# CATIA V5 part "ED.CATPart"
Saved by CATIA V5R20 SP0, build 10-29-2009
Part number: ED
Material "Or": density 19320 kg/m3, Young's modulus 7.8e+10 Pa, Poisson ratio 0.42, thermal expansion 1.42e-05 1/K
Bounding box of the stored display mesh (mm): x -35.216 to 14.383, y -1.883 to 23.533, z 0 to 2
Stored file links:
  D:\IAO\22janv\ED.CATPart
  D:\IAO\22janv\czortea.CATProduct
  C:\Program Files\Dassault Systemes\B20\win_b64\startup\materials\French\Catalog.CATMaterial
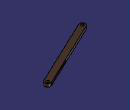
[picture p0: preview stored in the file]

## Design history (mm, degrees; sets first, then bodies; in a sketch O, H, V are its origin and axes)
External parameters (linked from other documents)
  External.epaisseur = 2 mm
Set1
  Plane1 "plan_ref": linked copy from another document
  Point1 "E": linked copy from another document
  Point2 "D": linked copy from another document
Body1 (main body), material "Or"
  Sketch1 on Plane1, origin (0, 0, 0), H (1, 0, 0), V (0, 1, 0)
    construction line L1 (-33.3333, 0) -> (12.5, 21.6506)
    point P1 (-33.3333, 0)
    point P2 (12.5, 21.6506)
    line L2 (-34.1876, 1.8084) -> (11.6458, 23.459)
    line L3 (13.3542, 19.8422) -> (-32.4791, -1.8084)
    arc A1 centre (12.5, 21.6506) radius 2 from (11.6458, 23.459) to (13.3542, 19.8422) cw
    arc A2 centre (-33.3333, 0) radius 2 from (-32.4791, -1.8084) to (-34.1876, 1.8084) cw
    reference projected point E1 (-33.3333, 0) from Point1
    reference projected point E2 (12.5, 21.6506) from Point2
    distance L1 L2 = 2 {= External.epaisseur}
    tangency: A1 L2, A2 L2, A1 L3, A2 L3
    coincidence: P1 E1, P2 E2
  Pad1: profile Sketch1, direction (0, 0, 1), length 2 {= External.epaisseur}
  Sketch2 on end face of Pad1, origin (-13.8524, 8.1093, 2), H (1, 0, 0), V (0, 1, 0)
    point P1 (26.3524, 13.5413)
    reference projected point E1 (26.3524, 13.5413) from Point2
    coincidence: P1 E1
  Hole1: placed by Sketch2, at (12.5, 21.6506, 2) direction (0, 0, -1), diameter 2 {= External.epaisseur}, through (limit type 6)
  Sketch3 on end face of Pad1, origin (-8.4471, 11.358, 2), H (1, 0, 0), V (0, 1, 0)
    point P1 (-24.8862, -11.358)
    reference projected point E1 (-24.8862, -11.358) from Point1
    coincidence: P1 E1
  Hole2: placed by Sketch3, at (-33.3333, 0, 2) direction (0, 0, -1), diameter 2 {= External.epaisseur}, through (limit type 6)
